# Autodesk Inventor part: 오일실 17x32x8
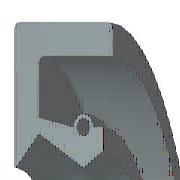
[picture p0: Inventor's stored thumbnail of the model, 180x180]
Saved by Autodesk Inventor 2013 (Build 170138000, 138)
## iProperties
IsCustomPart: 1
Company: 한국ATC센터
Created: 2014-07
Part Number: 오일실 17x32x8
Material: Rubber
Description: 오일-실
Document SubType Name: Modeling
Standard: KS B 2804
Designer: KYOUNG IL JANG
Standards Organization: KS
Language: ko-KR
Size Designation: D - 17 32 8
Categories: <MemberInstance><Categories><Category DisplayName="샤프트 부품" InternalName="7f7aeb1f-a693-4053-b835-cee3144e0d98" Mnemonic="SHFT"><Category DisplayName="실링" Intern
Density: 0.93 g/cm^3
Author: KYOUNG IL JANG
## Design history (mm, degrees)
revolve "본체" stored, may be unused: angle "d17" = 90 deg
revolve "스프링1" stored, may be unused: angle "d18" = 90 deg
body "Solid1"
sketch "스케치1"
  geometry: L1 (0, 16)-(8, 16); L2 (8, 14.25)-(1.75, 14.25); L3 (1.75, 10.25)-(4.9, 8.5); L4 (4.9, 8.5)-(0, 8.5); L5 (0, 0)-(9.586, 0) reference; L6 (4.9, 8.5)-(6.3, 9.375); L7 (0, 18)-(0, -3) reference; L8 (-1.941, 0)-(11.507, 0) reference; L9 (4.2, 10.6)-(1.75, 11.21); L10 (1.75, 11.21)-(1.75, 14.25); L11 (0, 16)-(0, 8.588); L12 (4.9, 8.5)-(0, 8.5); L13 (1.75, 10.25)-(0.152, 8.528); L14 (8, 16)-(8, 14.25); L15 (5.6, 10.6)-(6.3, 10.6); L16 (6.3, 10.6)-(6.3, 9.375); C1 r 0.455 at (4.9, 10.6); A1 r 0.7 centre (4.9, 10.6) between (5.6, 10.6) and (4.2, 10.6); A2 r 0.088 centre (0.088, 8.588) between (0, 8.588) and (0.152, 8.528); 1 further point
  constraints: 28 end point, 5 horizontal alignment, 5 point on line, 4 point on circle, 4 vertical alignment, 3 centre point, 3 tangent, 2 collinear, 2 horizontal, 2 perpendicular, 1 coincident, 1 parallel
  dimensions: "d0" = 32 diameter of L1 L5 (= SD2); "d1" = 1.75 distance of L1.end L2.start (= SD); "d2" = 0.91 diameter of C1 (= SPDI); "d3" = 1.4 diameter of A1 (= SPDA); "d4" = 17 diameter of L3.end L5 (= NND); "d5" = 20.5 diameter of L3.start L5 (= TKDM); "d7" = 22.42 diameter of L9.end L5 (= TKDM + 0.24 x SWDT); "d8" = 1.75 distance between parallel lines of L11 L10 (= SD); "d9" = 4.9 distance from line of L11 C1.centre (= SPDST); "d10" = 21.2 diameter of C1.centre L5 (= HLDM); "d11" = 0.0875 radius of A2 (= 0.25 x LAB); "d12" = 6.3 distance between parallel lines of L11 L16 (= SDI); "d13" = 18.75 diameter of L6.end L5 (= ABDM); "d14" = 8 distance from line of L11 L1.end (= SWDT)
fillet "모깎기1" dims "d6" = 0.3 (= RR)
other parameters: "SD2" = 32 [user parameter; used in 1 equation term], "SWDT" = 8 [user parameter; used in 2 equation terms], "RR" = 0.3 [user parameter; used in 1 equation term], "SD" = 1.75 [user parameter; used in 2 equation terms], "NND" = 17 [user parameter; used in 1 equation term], "SPDA" = 1.4 [user parameter; used in 1 equation term], "SPDI" = 0.91 [user parameter; used in 1 equation term], "TKDM" = 20.5 [user parameter; used in 2 equation terms], "HLDM" = 21.2 [user parameter; used in 1 equation term], "ABDM" = 18.75 [user parameter; used in 1 equation term], "SDI" = 6.3 [user parameter; used in 1 equation term], "SPDST" = 4.9 [user parameter; used in 1 equation term], "LAB" = 0.35 [user parameter; used in 1 equation term], "d15" = 0, "d16" = 0, "d19" = 0
